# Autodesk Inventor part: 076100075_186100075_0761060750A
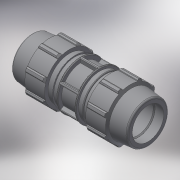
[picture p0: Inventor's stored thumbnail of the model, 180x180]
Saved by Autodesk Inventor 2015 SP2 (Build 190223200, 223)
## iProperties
Created: 2017-02
Part Number: 076100075_186100075_0761060750A
Material: Generic
Description: PLASSON REPAIR COUPLER 75
Document SubType Name: Modeling
Designer: KIM
Mass: 1641.18 g
Surface Area: 2112.15 cm^2
Volume: 1641.18 cm^3
Density: 1 g/cm^3
Appearance: Default
Author: KIM
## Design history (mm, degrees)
derived "07610.ipt"
feature "Solid1::07610.ipt"
tag "TaggingFeature1"
body "Solid1"
other parameters: "d1" = 278, "d2" = 75, "d4" = 23.16667, "d5" = 39.71429, "d7" = 134, "d8" = 100.5, "d9" = 39.71429, "d11" = 3.48571, "d12" = 107.2, "d13" = 120 deg, "d14" = 105, "d15" = 6 deg, "d16" = 120.6, "d18" = 3.75, "d19" = 35 deg, "d20" = 17.5 deg, "d21" = 124.62, "d23" = 0, "d25" = 360 deg, "d27" = 2.68, "d33" = 1.5, "d34" = 6.7, "d36" = 0, "d37" = 1.5, "d38" = 1.5, "d40" = 360 deg, "d42" = 50.04, "d43" = 4.02, "d46" = 2.25, "d50" = 10.96571, "d51" = 107.2, "d_" = 75, "E_" = 134, "H_" = 278, "l_" = 139, "d49" = 25.41714
